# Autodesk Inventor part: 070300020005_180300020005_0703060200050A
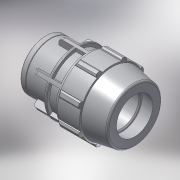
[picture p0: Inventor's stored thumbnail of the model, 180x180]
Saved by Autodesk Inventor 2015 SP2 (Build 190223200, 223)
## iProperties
Created: 2017-02
Part Number: 070300020005_180300020005_0703060200050A
Material: PVC-Piping
Description: PLASSON FEMALE ADAPTOR 20-1/2"
Document SubType Name: Modeling
Designer: KIM
Mass: 92.6774 g
Surface Area: 199.44 cm^2
Volume: 66.1981 cm^3
Density: 1.4 g/cm^3
Appearance: Smooth - White
Author: KIM
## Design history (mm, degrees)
derived "07030.ipt"
feature "Solid1::07030.ipt"
tag "TaggingFeature1"
body "Solid1"
other parameters: "d4" = 11.71429, "d5" = 20.5, "d7" = 48, "d9" = 11.71429, "d11" = 2.34286, "d12" = 38.4, "d13" = 120 deg, "d15" = 12 deg, "d16" = 43.2, "d18" = 1, "d19" = 35 deg, "d20" = 17.5 deg, "d21" = 44.64, "d23" = 0, "d25" = 360 deg, "d27" = 0.96, "d34" = 2.4, "d35" = 24.6, "d36" = 0, "d42" = 20.5, "d43" = 1.44, "d46" = 0.6, "d51" = 82, "d53" = 0.4, "d55" = 360 deg, "d61" = 19, "d62" = 16, "d63" = 18.631, "d64" = 27.33333, "d65" = 2.4, "d66" = 0.5, "d67" = 1, "d68" = 5.7, "d69" = 34.56, "d70" = 1.2, "E_" = 48, "H_" = 82, "l_2" = 19, "Rp_" = 18.631
